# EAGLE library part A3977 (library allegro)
MICROSTEPPING DMOS DRIVER WITH TRANSLATOR Source: 3977.pdf
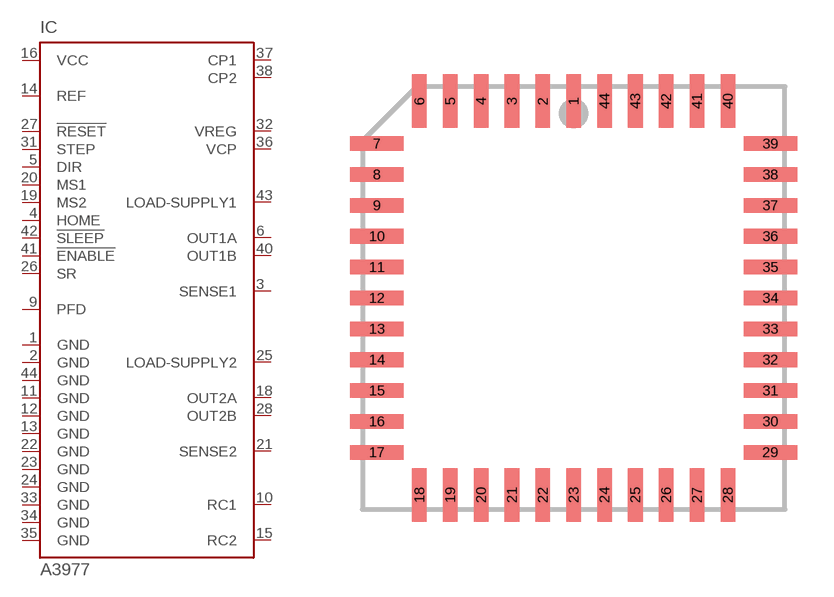
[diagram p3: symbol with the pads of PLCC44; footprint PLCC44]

Designator prefix IC

## A3977 (MF: ALLEGRO MICROSYSTEMS, INC.; MPN: A3977SED-T; OC_FARNELL: 1198089; OC_NEWARK: 31K6655)  [PLCC44]
1  GND  pwr
2  GND  pwr
3  SENSE1  in
4  HOME  in
5  DIR  in
6  OUT1A  out
9  PFD  in
10  RC1  in
11  GND  pwr
12  GND  pwr
13  GND  pwr
14  REF  in
15  RC2  in
16  VCC  pwr
18  OUT2A  out
19  MS2  in
20  MS1  in
21  SENSE2  in
22  GND  pwr
23  GND  pwr
24  GND  pwr
25  LOAD-SUPPLY2  in
26  SR  in
27  !RESET  in
28  OUT2B  out
31  STEP  in
32  VREG  in
33  GND  pwr
34  GND  pwr
35  GND  pwr
36  VCP  in
37  CP1  in
38  CP2  in
40  OUT1B  out
41  !ENABLE  in
42  !SLEEP  in
43  LOAD-SUPPLY1  in
44  GND  pwr

## Footprint PLCC44 (pad centres in mm)
PLASTIC LEADED CHIP CARRIER square
smd 0.6 x 2.2: 1 0,8.1; 2 -1.27,8.1; 3 -2.54,8.1; 4 -3.81,8.1; 5 -5.08,8.1; 6 -6.35,8.1; 18 -6.35,-8.1; 19 -5.08,-8.1; 20 -3.81,-8.1; 21 -2.54,-8.1; 22 -1.27,-8.1; 23 0,-8.1; 24 1.27,-8.1; 25 2.54,-8.1; 26 3.81,-8.1; 27 5.08,-8.1; 28 6.35,-8.1; 40 6.35,8.1; 41 5.08,8.1; 42 3.81,8.1; 43 2.54,8.1; 44 1.27,8.1
smd 2.2 x 0.6: 7 -8.1,6.35; 8 -8.1,5.08; 9 -8.1,3.81; 10 -8.1,2.54; 11 -8.1,1.27; 12 -8.1,0; 13 -8.1,-1.27; 14 -8.1,-2.54; 15 -8.1,-3.81; 16 -8.1,-5.08; 17 -8.1,-6.35; 29 8.1,-6.35; 30 8.1,-5.08; 31 8.1,-3.81; 32 8.1,-2.54; 33 8.1,-1.27; 34 8.1,0; 35 8.1,1.27; 36 8.1,2.54; 37 8.1,3.81; 38 8.1,5.08; 39 8.1,6.35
